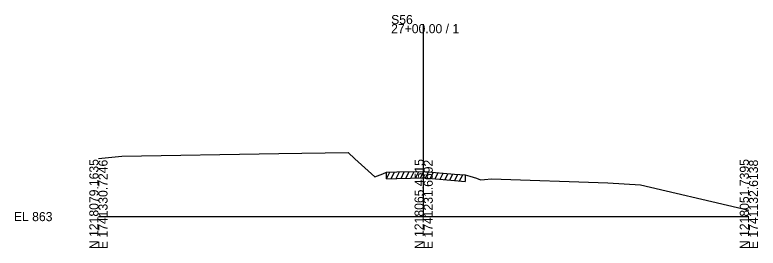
# Model space of a CAD drawing. Extents: x -26 to 1203, y -10 to 19541.
# Drawn here: x -25.7 to 202.8, y 1990.3 to 2062 of the extents above; entities that cross this region are included whole.
import ezdxf

# ---------------------------------------------------------------- set-up
doc = ezdxf.new("R2010")
doc.units = 0
for name, color, linetype in [('RD_GPK_XS_Cell', 7, 'Continuous'), ('RD_XS_ExGround', 7, 'Continuous'), ('RD_XS_ExPaveRet', 7, 'Continuous'), ('RD_XS_TX_Elev_EX', 7, 'Continuous')]:
    doc.layers.add(name, color=color, linetype=linetype)

msp = doc.modelspace()

# ---------------------------------------------------------------- linework, layer by layer
at = {"layer": 'RD_GPK_XS_Cell'}
for p, q in [((100, 2000), (100, 2059.19)), ((0, 2000), (100, 2000)), ((100, 2000), (200, 2000))]:
    msp.add_line(p, q, dxfattribs=at)
at = {"layer": 'RD_XS_ExGround'}
msp.add_lwpolyline([(0, 2017.9), (7.16, 2018.63), (55.51, 2019.41), (76.77, 2019.73), (78.82, 2017.81), (84.96, 2012.18), (87.46, 2013.19), (88.54, 2013.65), (91.77, 2013.73), (100.12, 2013.9), (109.53, 2013.1), (112.81, 2012.8), (114.23, 2012.39), (116.25, 2011.79), (117.44, 2011.26), (118.67, 2011.42), (120.81, 2011.65), (156.62, 2010.43), (166.69, 2009.82), (196.5, 2002.81), (200, 2001.96)], dxfattribs=at)
at = {"layer": 'RD_XS_ExPaveRet'}
for p, q in [((88.54, 2011.65), (89.56, 2013.67)), ((88.54, 2011.65), (88.54, 2013.65)), ((90.04, 2011.69), (91.06, 2013.71)), ((91.54, 2011.73), (92.55, 2013.75)), ((93.04, 2011.76), (94.05, 2013.78)), ((94.54, 2011.79), (95.55, 2013.81)), ((96.04, 2011.82), (97.05, 2013.84)), ((97.54, 2011.85), (98.55, 2013.87)), ((99.04, 2011.88), (100.05, 2013.9)), ((100.54, 2011.87), (101.5, 2013.78)), ((102.04, 2011.74), (103, 2013.66)), ((103.54, 2011.61), (104.5, 2013.53)), ((105.04, 2011.48), (106, 2013.4)), ((88.54, 2011.65), (91.77, 2011.73)), ((91.77, 2011.73), (100.12, 2011.9)), ((100.12, 2011.9), (109.53, 2011.1)), ((106.54, 2011.35), (107.5, 2013.27)), ((108.04, 2011.23), (109, 2013.14)), ((109.53, 2011.1), (112.81, 2010.8)), ((109.54, 2011.1), (110.5, 2013.01)), ((111.04, 2010.96), (112, 2012.87)), ((112.81, 2012.8), (112.81, 2010.8))]:
    msp.add_line(p, q, dxfattribs=at)

# ---------------------------------------------------------------- texts
at = {"layer": 'RD_GPK_XS_Cell'}
for s, p in [('S56', (90, 2059.19)), ('27+00.00 / 1', (90, 2056.39)), ('EL 863', (-26, 1998.6))]:
    msp.add_text(s, height=2.8, dxfattribs=at).set_placement(p)
for s, p in [('N 1218079.1635', (0, 1990)), ('E 1741330.7246', (2.8, 1990)), ('N 1218065.4515', (100, 1990)), ('E 1741231.6692', (102.8, 1990)), ('N 1218051.7395', (200, 1990)), ('E 1741132.6138', (202.8, 1990))]:
    msp.add_text(s, height=2.8, rotation=90, dxfattribs=at).set_placement(p)
at = {"layer": 'RD_XS_TX_Elev_EX'}
msp.add_text('869.95', height=0.1, rotation=90, dxfattribs=at).set_placement((100.1, 2013.9))

doc.saveas('drawing.dxf')
